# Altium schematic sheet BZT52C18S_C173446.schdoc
size 127 x 101 mm
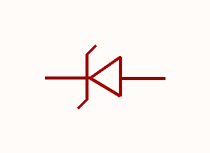
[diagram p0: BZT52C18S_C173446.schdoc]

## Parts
D?  bzt52c18s_c173446  [SOD-323_L1.8-W1.3-LS2.5-RD]  (value not drawn)

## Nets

Not connected (* = marked no-connect by the designer): D? 1(K) 2(A)

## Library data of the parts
D? = bzt52c18s_c173446: 二极管配置:1个独立式;稳压值(标称值):18V;稳压值(范围):16.8V~19.1V;耗散功率(Pd):200mW;; Manufacturer: MDD(辰达半导体); AddInBom: yes; ModelId: db63db13d9e342eb939127d413d6200b; ModelTransform: 104.3305,51.181,0,0,0,0,0,-0.004,0; Diode Configuration: 1个独立式; Zener Voltage(Nom): 18V; Reverse Leakage Current (Ir): 100nA@13V; Pd - Power Dissipation: 200mW; Impedance(Zzt): 45Ω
